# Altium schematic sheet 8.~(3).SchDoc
size 420 x 297 mm
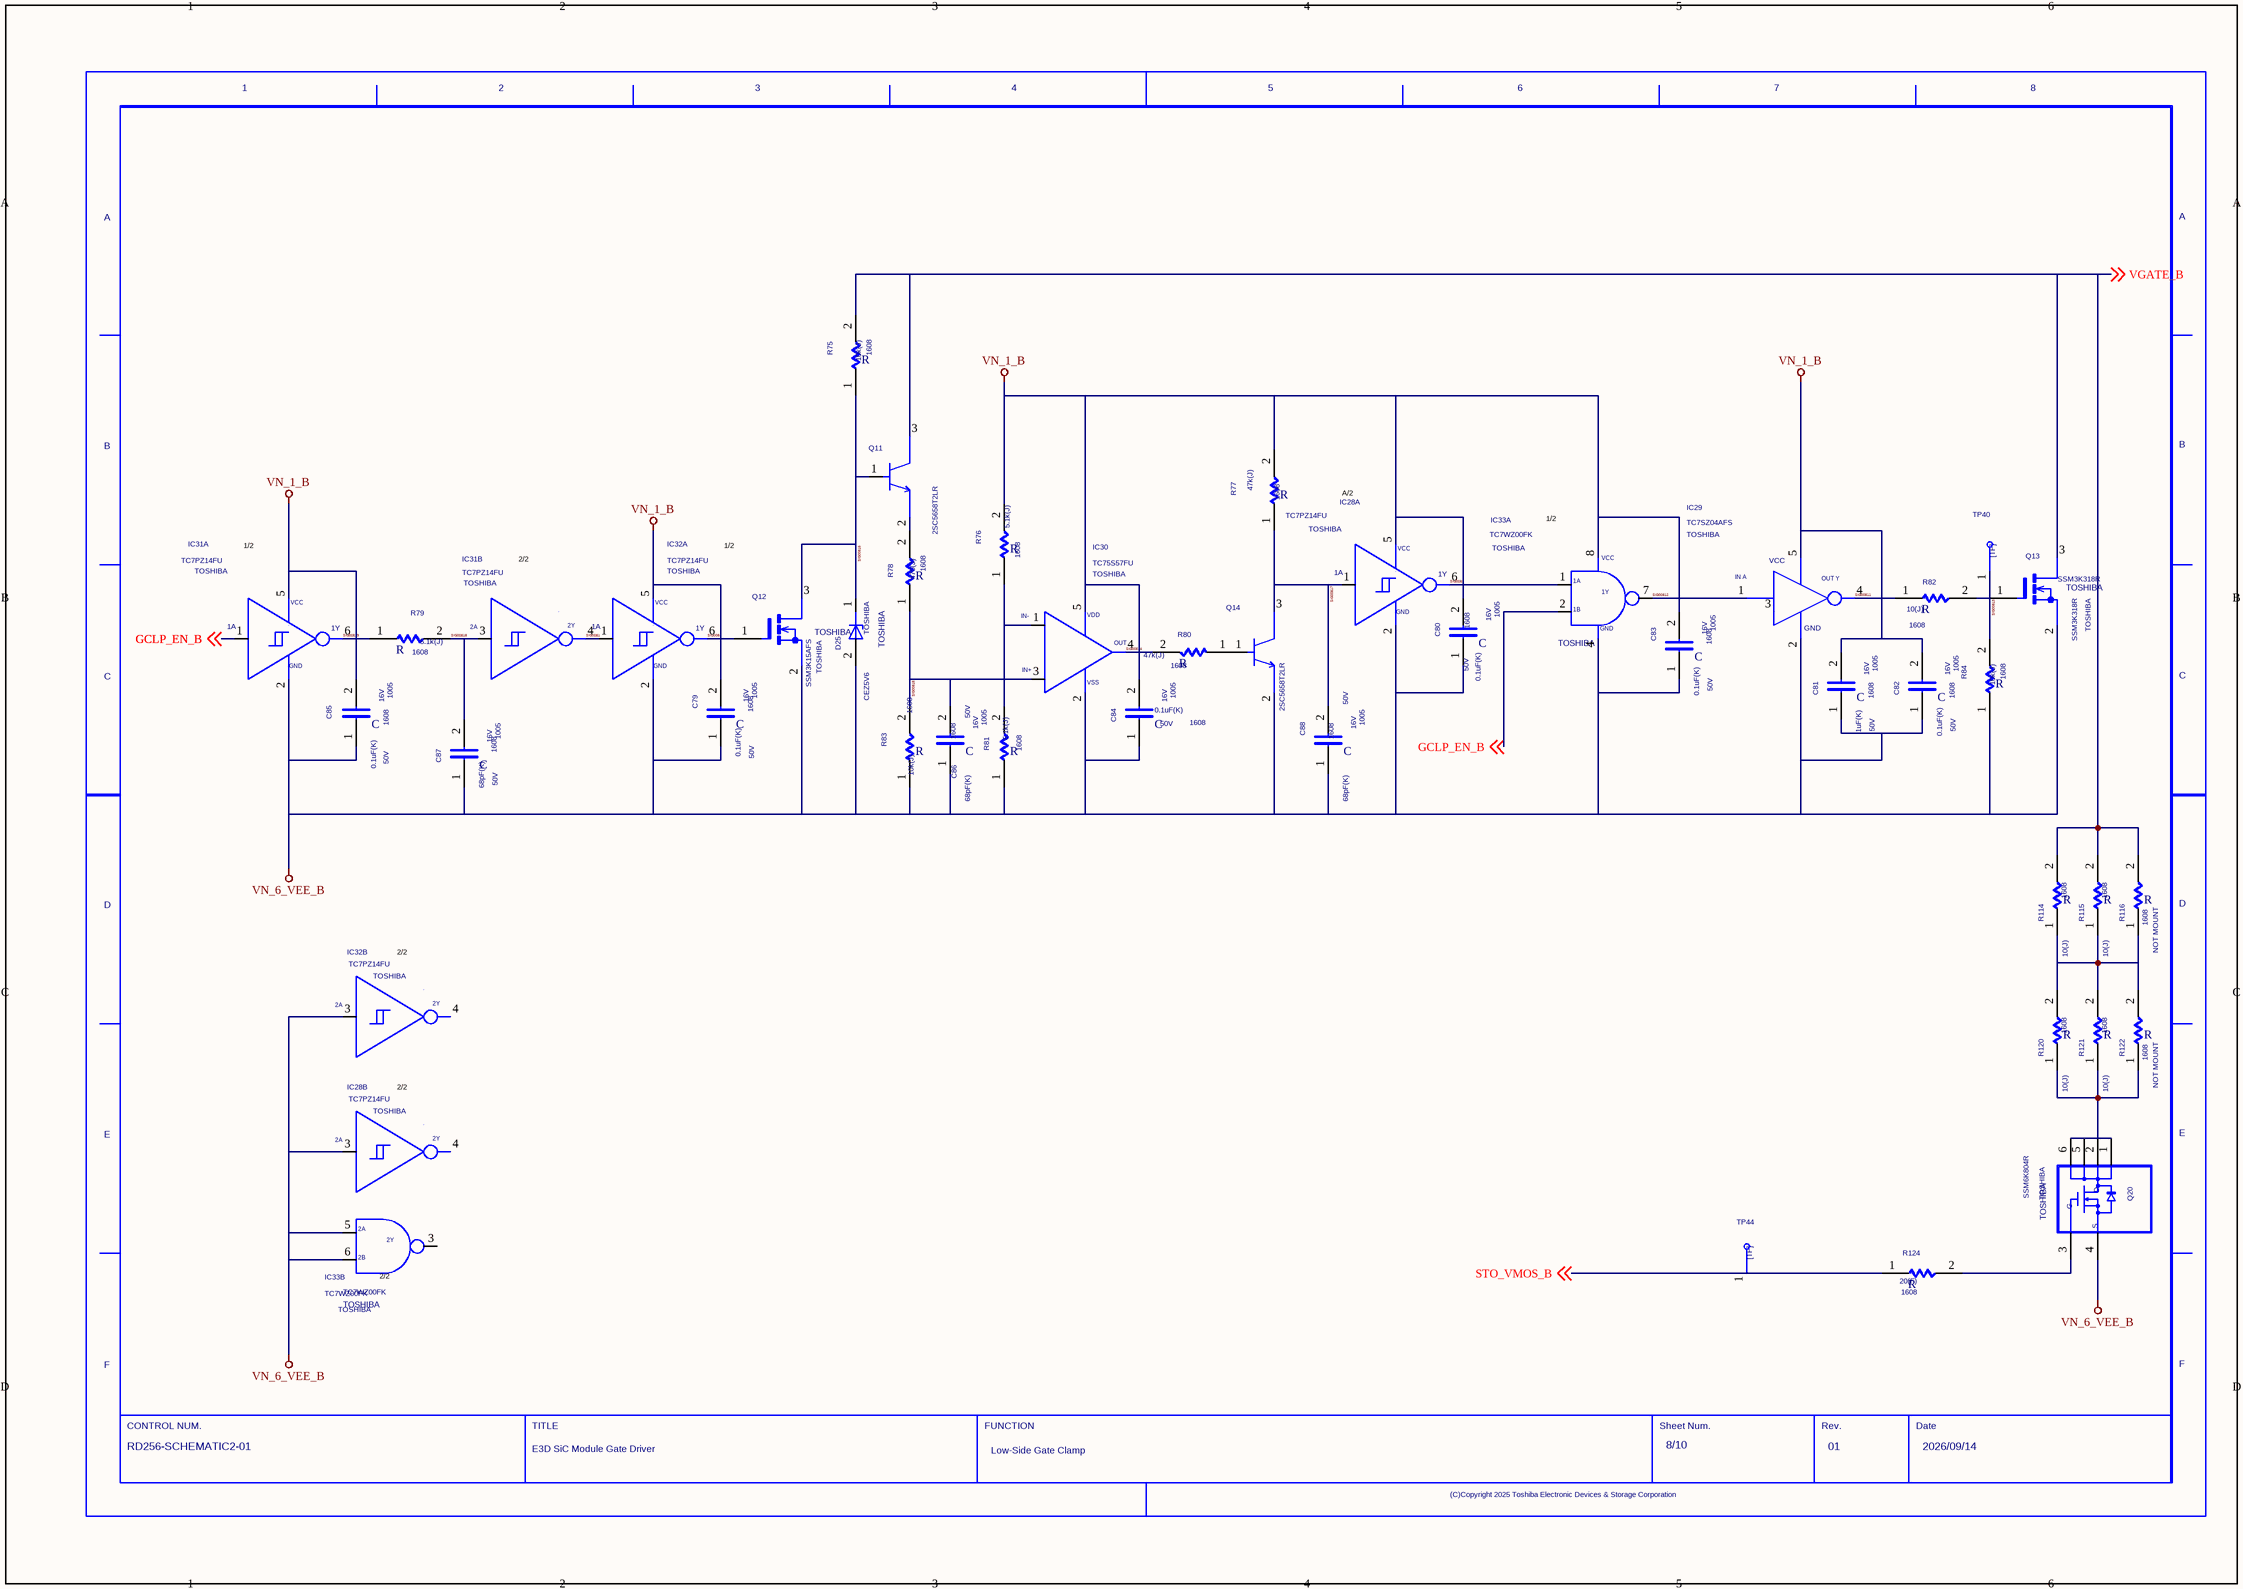
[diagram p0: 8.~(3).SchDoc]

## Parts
C79  VOLTAGE: 16V  CODE: 1005  VAL1: 0.1uF(K)  VAL2: 50V  SIZECODESMD: 1608  (hidden comment: C)
C80  VOLTAGE: 16V  CODE: 1005  VAL1: 0.1uF(K)  VAL2: 50V  SIZECODESMD: 1608  (hidden comment: C)
C81  VOLTAGE: 16V  CODE: 1005  VAL1: 1uF(K)  VAL2: 50V  SIZECODESMD: 1608  (hidden comment: C)
C82  VOLTAGE: 16V  CODE: 1005  VAL1: 0.1uF(K)  VAL2: 50V  SIZECODESMD: 1608  (hidden comment: C)
C83  VOLTAGE: 16V  CODE: 1005  VAL1: 0.1uF(K)  VAL2: 50V  SIZECODESMD: 1608  (hidden comment: C)
C84  VOLTAGE: 16V  CODE: 1005  VAL1: 0.1uF(K)  VAL2: 50V  SIZECODESMD: 1608  (hidden comment: C)
C85  VOLTAGE: 16V  CODE: 1005  VAL1: 0.1uF(K)  VAL2: 50V  SIZECODESMD: 1608  (hidden comment: C)
C86  VOLTAGE: 16V  CODE: 1005  VAL1: 68pF(K)  VAL2: 50V  SIZECODESMD: 1608  (hidden comment: C)
C87  VOLTAGE: 16V  CODE: 1005  VAL1: 68pF(K)  VAL2: 50V  SIZECODESMD: 1608  (hidden comment: C)
C88  VOLTAGE: 16V  CODE: 1005  VAL1: 68pF(K)  VAL2: 50V  SIZECODESMD: 1608  (hidden comment: C)
D25  VENDOR: TOSHIBA  (hidden comment: CEZ5V6)
IC28  VAL3: TC7PZ14FU  USERCOMPTEXT3: TOSHIBA  (hidden comment: TC7PZ17FU)  (parts A,B of 2)
IC29  USERCOMPTEXT3: TOSHIBA  (hidden comment: TC7SZ04AFS)
IC30  USERCOMPTEXT3: TOSHIBA  (hidden comment: TC75S57FU)
IC31  VAL3: TC7PZ14FU  USERCOMPTEXT3: TOSHIBA  (hidden comment: TC7PZ17FU)  (parts A,B of 2)
IC32  VAL3: TC7PZ14FU  USERCOMPTEXT3: TOSHIBA  (hidden comment: TC7PZ17FU)  (parts A,B of 2)
IC33  VENDOR: TOSHIBA  (hidden comment: TC7WZ00FK)  (parts A,B of 2)
Q11  VAL3: 2SC5658T2LR  (hidden comment: 2SC5658J)
Q12  VENDOR: TOSHIBA  (hidden comment: SSM3K15AFS)
Q13  VENDOR: TOSHIBA  (hidden comment: SSM3K318R)
Q14  VAL3: 2SC5658T2LR  (hidden comment: 2SC5658J)
Q20  VENDOR: TOSHIBA  (hidden comment: SSM6K804R)
R75  VAL1: 10k(J)  SIZECODESMD: 1608  (hidden comment: R)
R76  VAL1: 5.1k(J)  SIZECODESMD: 1608  (hidden comment: R)
R77  VAL1: 47k(J)  SIZECODESMD: 1608  (hidden comment: R)
R78  VAL1: 470(J)  SIZECODESMD: 1608  (hidden comment: R)
R79  VAL1: 5.1k(J)  SIZECODESMD: 1608  (hidden comment: R)
R80  VAL1: 47k(J)  SIZECODESMD: 1608  (hidden comment: R)
R81  VAL1: 5.1k(J)  SIZECODESMD: 1608  (hidden comment: R)
R82  VAL1: 10(J)  SIZECODESMD: 1608  (hidden comment: R)
R83  VAL1: 10k(J)  SIZECODESMD: 1608  (hidden comment: R)
R84  VAL1: 10k(J)  SIZECODESMD: 1608  (hidden comment: R)
R114  VAL1: 10(J)  SIZECODESMD: 1608  (hidden comment: R)
R115  VAL1: 10(J)  SIZECODESMD: 1608  (hidden comment: R)
R116  SIZECODESMD: 1608  NOTMOUNT: NOT MOUNT  (hidden comment: R)
R120  VAL1: 10(J)  SIZECODESMD: 1608  (hidden comment: R)
R121  VAL1: 10(J)  SIZECODESMD: 1608  (hidden comment: R)
R122  SIZECODESMD: 1608  NOTMOUNT: NOT MOUNT  (hidden comment: R)
R124  VAL1: 20(F)  SIZECODESMD: 1608  (hidden comment: R)
TP40  TP  (value not drawn)
TP44  TP  (value not drawn)
U?  REVISION: 01  SHEETNUMBER: 8/10  FUNCTION: Low-Side Gate Clamp  TITLE: E3D SiC Module Gate Driver  DRAWINGNUMBER: RD256-SCHEMATIC2-01  DATE: 2026/09/14  (hidden comment: WAKU_DEF100)

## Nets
VN_1_B: C79.2 C80.2 C81.2 C82.2 C83.2 C84.2 C85.2 IC28.5 IC29.5 IC30.5 IC31.5 IC32.5 IC33.8 R76.2 R77.2
VN_6_VEE_B: C79.1 C80.1 C81.1 C82.1 C83.1 C84.1 C85.1 C86.1 C87.1 C88.1 D25.2(A) IC28.2 IC28.3 IC29.2 IC30.2 IC31.2 IC32.2 IC32.3 IC33.4 IC33.5(2A) IC33.6(2B) Q12.2(S) Q13.2(S) Q14.2(E) Q20.4 R81.1 R83.1 R84.1
GCLP_EN_B: IC31.1 IC33.2 ; off-sheet GCLP_EN_B
SIG0081: IC31.4 IC32.1
SIG0082: Q20.3 R124.2
SIG0083: R114.1 R115.1 R116.1 R120.2 R121.2 R122.2
SIG0084: IC32.6 Q12.1(G)
SIG0085: IC28.6 IC33.1
SIG0086: IC30.1 R76.1 R81.2
SIG0089: Q11.2(E) R78.2
SIG00810: Q20.1 Q20.2 Q20.5 Q20.6 R120.1 R121.1 R122.1
SIG00811: IC29.4 R82.1
SIG00812: IC29.1 IC33.7
SIG00813: Q13.1(G) R82.2 R84.2 TP40.1
SIG00814: IC30.4 R80.2
SIG00815: C86.2 IC30.3 R78.1 R83.2
SIG00816: D25.1(C) Q11.1(B) Q12.3(D) R75.1
SIG00817: C88.2 IC28.1 Q14.3(C) R77.1
SIG00818: C87.2 IC31.3 R79.2
SIG00819: IC31.6 R79.1
STO_VMOS_B: R124.1 TP44.1 ; off-sheet STO_VMOS_B
VGATE_B: Q11.3(C) Q13.3(D) R75.2 R114.2 R115.2 R116.2 ; off-sheet VGATE_B
NetQ14_1: Q14.1(B) R80.1

Not connected (* = marked no-connect by the designer): IC28 4; IC29 3; IC32 4; IC33 3(2Y)

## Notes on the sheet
- A/2
- (near IC33) 1/2
- (near IC31) 1/2
- 2/2
- 1/2
- (near IC33) 2/2

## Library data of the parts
C79-C88 = C: ORIGINALSYMBOLORIGIN: (0,0); VC2: 0; PSPICETEMPLATE: C^@REFDES %1 %2 ?TOLERANCE¦C^@REFDES¦ @VALUE ?IC/IC=@IC/ TC=@TC1,@TC2 ?TOLERANCE¦\n.model C^@REFDES CAP C=1 DEV=@TOLERANCE% TC1=@TC1 TC2=@TC2 VC1=@VC1 VC2=@VC2¦; SAVECOUNT: 2; UPDATETIME: 08:48:12; UPDATEUSER: HP_Z8_KEYSHOT; INSTANCENAME: INS2265204
D25 = CEZ5V6: ORIGINALSYMBOLORIGIN: (0,0); PSPICETEMPLATE: X^@REFDES %C %A @MODEL; SAVEAREA0: -4630,-153,17114,13055; SAVECOUNT: 9; UPDATETIME: 08:16:22; UPDATEUSER: fukuda-y; TIME: 14:49:55; INSTANCENAME: INS2262356
IC28 IC31 IC32 = TC7PZ14FU_2: OriginalSymbolOrigin: (5080,15240); SWAP_INFO: (S1+S2); PSPICETEMPLATE: X^@REFDES %1A %GND %2A %2Y %VCC %1Y @MODEL; SPLIT_INST: TRUE; SAVECOUNT: 7; UPDATETIME: 19:09:34; UPDATEUSER: t5459927; TIME: 11:55:01; FUNCN: TC7PZ14FU_1; CaptureCellPackProp: TC7PZ14FU_2A
IC29 = TC7SZ04AFS: OriginalSymbolOrigin: (0,-5080); PSPICETEMPLATE: X^@REFDES %INA %GND %NC %OUTY %VCC @MODEL; SAVECOUNT: 6; UPDATETIME: 19:30:29; UPDATEUSER: t5459927; TIME: 11:55:02; INSTANCENAME: INS2262788
IC30 = TC75S57FU: OriginalSymbolOrigin: (2540,0); PSPICETEMPLATE: X^@REFDES %INN %VSS %INP %OUT %VDD @MODEL; SAVECOUNT: 3; UPDATETIME: 11:03:38; UPDATEUSER: t5459927; TIME: 08:48:15; INSTANCENAME: INS2262824
IC33 = TC7WZ00FK_2: PART NUMBER: TC7W00FK; ORIGINALSYMBOLORIGIN: (2540,-2540); DESCRIPTION-A: NAND 2ch Logic; PSPICETEMPLATE: X^@REFDES %1A %1B %2Y %GND %2A %2B %1Y %VCC @MODEL; ・: 7 V; SPLIT_INST: TRUE; ORDER: $pOrder; SWAP_INFO: (S1+S2); SAVECOUNT: 5; UPDATETIME: 16:09:46; UPDATEUSER: sptcae09; TIME: 08:52:39; FUNCN: TC7WZ00FK_1; CaptureCellPackProp: TC7WZ00FK_2A
Q11 = 2SC5658J: ORIGINALSYMBOLORIGIN: (0,0); PSPICETEMPLATE: X^@REFDES %C %B %E @MODEL; SAVEAREA0: -6194,-158,18648,15662; VENDOR: ROHM; SAVECOUNT: 8; UPDATETIME: 15:12:10; UPDATEUSER: 19910145; TIME: 09:39:04; INSTANCENAME: INS2262598
Q12 = SSM3K15AFS: PSPICETEMPLATE: X^@REFDES %D %G %S @MODEL; ORIGINALSYMBOLORIGIN: (0,0); SAVECOUNT: 2; UPDATETIME: 08:48:15; UPDATEUSER: HP_Z8_KEYSHOT; INSTANCENAME: INS2262996
Q13 = SSM3K318R: PSPICETEMPLATE: X^@REFDES %D %G %S @MODEL; ORIGINALSYMBOLORIGIN: (0,0); SAVECOUNT: 2; UPDATETIME: 08:48:16; UPDATEUSER: HP_Z8_KEYSHOT; INSTANCENAME: INS2261964
Q14 = 2SC5658J: ORIGINALSYMBOLORIGIN: (0,0); PSPICETEMPLATE: X^@REFDES %C %B %E @MODEL; SAVEAREA0: -6194,-158,18648,15662; VENDOR: ROHM; SAVECOUNT: 8; UPDATETIME: 15:12:10; UPDATEUSER: 19910145; TIME: 09:39:04; INSTANCENAME: INS2262860
Q20 = SSM6K804R: PSPICETEMPLATE: X^@REFDES %1 %2 %3 %4 %5 %6 @MODEL; ORIGINALSYMBOLORIGIN: (0,0); SAVEAREA0: -7120,-295,29516,23636; SAVECOUNT: 14; UPDATETIME: 08:48:15; UPDATEUSER: HP_Z8_KEYSHOT; INSTANCENAME: INS2262956
R75-R81 R83 R84 R114 R115 R120 R121 R124 = R: ORIGINALSYMBOLORIGIN: (0,0); PSPICETEMPLATE: R^@REFDES %1 %2 ?TOLERANCE¦R^@REFDES¦ @VALUE TC=@TC1,@TC2 ?TOLERANCE¦\n.model R^@REFDES RES R=1 DEV=@TOLERANCE% TC1=@TC1 TC2=@TC2¦; TC2: 0; VAL2: 100mW; SAVECOUNT: 2; UPDATETIME: 08:48:13; UPDATEUSER: HP_Z8_KEYSHOT; INSTANCENAME: INS2263832
R82 = R: ORIGINALSYMBOLORIGIN: (0,0); PSPICETEMPLATE: R^@REFDES %1 %2 ?TOLERANCE¦R^@REFDES¦ @VALUE TC=@TC1,@TC2 ?TOLERANCE¦\n.model R^@REFDES RES R=1 DEV=@TOLERANCE% TC1=@TC1 TC2=@TC2¦; TC2: 0; VAL2: 100mW; SAVECOUNT: 2; UPDATETIME: 08:48:13; UPDATEUSER: HP_Z8_KEYSHOT; INSTANCENAME: INS2262084
R116 R122 = R: ORIGINALSYMBOLORIGIN: (0,0); PSPICETEMPLATE: R^@REFDES %1 %2 ?TOLERANCE¦R^@REFDES¦ @VALUE TC=@TC1,@TC2 ?TOLERANCE¦\n.model R^@REFDES RES R=1 DEV=@TOLERANCE% TC1=@TC1 TC2=@TC2¦; TC2: 0; VAL2: 0.125; SAVECOUNT: 2; UPDATETIME: 08:48:13; UPDATEUSER: HP_Z8_KEYSHOT; INSTANCENAME: INS2263832
TP40 = TP: ORIGINALSYMBOLORIGIN: (0,0); SAVEAREA0: -242,-92,12810,7836; SAVECOUNT: 2; UPDATETIME: 16:18:11; UPDATEUSER: fukuda-y; TIME: 16:12:21; INSTANCENAME: INS2262622
TP44 = TP: ORIGINALSYMBOLORIGIN: (0,0); SAVEAREA0: -242,-92,12810,7836; SAVECOUNT: 2; UPDATETIME: 16:18:11; UPDATEUSER: fukuda-y; TIME: 16:12:21; INSTANCENAME: INS2262916
U? = WAKU_DEF100: OriginalSymbolOrigin: (10160,284480); SAVECOUNT: 4; UPDATETIME: 12:22:01; UPDATEUSER: t5459927; TIME: 14:30:25; SAVEAREA0: -63393,-16950,474261,314592; PLOTTIME: HH:MM; SHTSAVECOUNT: 23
